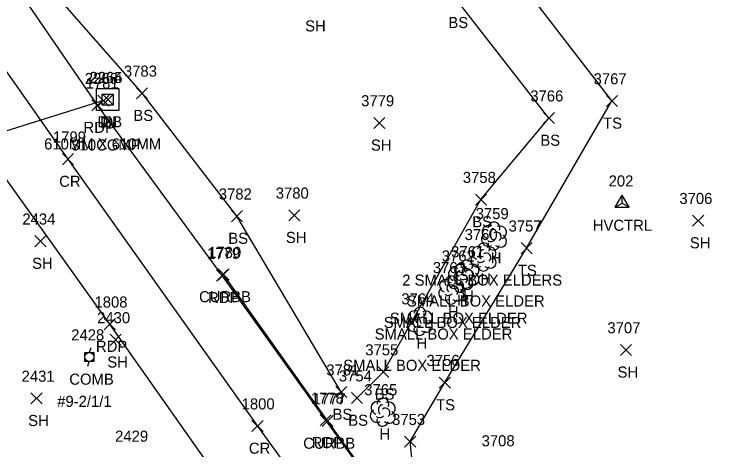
# Model space of a CAD drawing. Extents: x 1634209 to 1639641, y 608564 to 612258.
# Drawn here: x 1639024.2 to 1639153.3, y 611382 to 611460.6 of the extents above; entities that cross this region are included whole.
import ezdxf

# ---------------------------------------------------------------- set-up
doc = ezdxf.new("R2010")
doc.units = 0
for name, color, linetype in [('C_A', 7, 'Continuous'), ('C_I', 7, 'Continuous'), ('CPSM', 7, 'Continuous'), ('D_A', 7, 'Continuous'), ('D_C', 7, 'Continuous'), ('D_I', 7, 'Continuous'), ('D_TIC', 7, 'Continuous'), ('DCP', 7, 'Continuous'), ('DS', 7, 'Continuous'), ('L_A', 7, 'Continuous'), ('L_C', 7, 'Continuous'), ('L_I', 7, 'Continuous'), ('L_TIC', 7, 'Continuous'), ('LELB', 7, 'Continuous'), ('LTD', 7, 'Continuous'), ('P_A', 7, 'Continuous'), ('P_I', 7, 'Continuous'), ('P_TIC', 7, 'Continuous'), ('PET', 7, 'Continuous'), ('PRC', 7, 'Continuous'), ('R_A', 7, 'Continuous'), ('R_I', 7, 'Continuous'), ('R_TIC', 7, 'Continuous'), ('RC', 7, 'Continuous'), ('U_A', 7, 'Continuous'), ('U_C', 7, 'Continuous'), ('U_I', 7, 'Continuous'), ('UP', 7, 'Continuous')]:
    doc.layers.add(name, color=color, linetype=linetype)

msp = doc.modelspace()

# ---------------------------------------------------------------- linework, layer by layer
at = {"layer": 'CPSM'}
for p, q in [((1639132.51, 611425.81), (1639133.76, 611427.98)), ((1639135.01, 611425.81), (1639133.76, 611427.98)), ((1639133.76, 611426.54), (1639133.76, 611427.98)), ((1639132.51, 611425.81), (1639133.76, 611426.54)), ((1639132.51, 611425.81), (1639135.01, 611425.81)), ((1639133.76, 611426.54), (1639133.76, 611426.54)), ((1639133.76, 611426.54), (1639135.01, 611425.81))]:
    msp.add_line(p, q, dxfattribs=at)
at = {"layer": 'D_TIC'}
for points in [[(1639039.23, 611444.04), (1639041.23, 611446.04)], [(1639041.23, 611444.04), (1639039.23, 611446.04)], [(1639040.03, 611444.22), (1639042.03, 611446.22)], [(1639042.03, 611444.22), (1639040.03, 611446.22)]]:
    msp.add_lwpolyline(points, dxfattribs=at)
at = {"layer": 'DCP'}
msp.add_lwpolyline([(1639040.23, 611445.04), (1639009.01, 611435.28)], dxfattribs=at)
at = {"layer": 'DS'}
for p, q in [((1639038.98, 611447.23), (1639042.98, 611447.23)), ((1639038.98, 611443.23), (1639038.98, 611447.23)), ((1639039.98, 611444.23), (1639039.98, 611446.23)), ((1639039.98, 611446.23), (1639041.98, 611446.23)), ((1639041.98, 611446.23), (1639041.98, 611444.23)), ((1639042.98, 611447.23), (1639042.98, 611443.23)), ((1639040.98, 611445.23), (1639040.98, 611445.23)), ((1639040.98, 611445.23), (1639040.98, 611445.23)), ((1639041.98, 611444.23), (1639039.98, 611444.23)), ((1639042.98, 611443.23), (1639038.98, 611443.23))]:
    msp.add_line(p, q, dxfattribs=at)
at = {"layer": 'L_TIC'}
for points in [[(1639046.18, 611445.37), (1639048.18, 611447.37)], [(1639048.18, 611445.37), (1639046.18, 611447.37)], [(1639130.91, 611443.98), (1639132.91, 611445.98)], [(1639132.91, 611443.98), (1639130.91, 611445.98)], [(1639119.56, 611440.89), (1639121.56, 611442.89)], [(1639121.56, 611440.89), (1639119.56, 611442.89)], [(1639088.97, 611440.02), (1639090.97, 611442.02)], [(1639090.97, 611440.02), (1639088.97, 611442.02)], [(1639107.29, 611426.18), (1639109.29, 611428.18)], [(1639109.29, 611426.18), (1639107.29, 611428.18)], [(1639073.64, 611423.35), (1639075.64, 611425.35)], [(1639075.64, 611423.35), (1639073.64, 611425.35)], [(1639063.29, 611423.19), (1639065.29, 611425.19)], [(1639065.29, 611423.19), (1639063.29, 611425.19)], [(1639146.47, 611422.38), (1639148.47, 611424.38)], [(1639148.47, 611422.38), (1639146.47, 611424.38)], [(1639027.87, 611418.67), (1639029.87, 611420.67)], [(1639029.87, 611418.67), (1639027.87, 611420.67)], [(1639115.54, 611417.41), (1639117.54, 611419.41)], [(1639117.54, 611417.41), (1639115.54, 611419.41)], [(1639041.43, 611400.86), (1639043.43, 611402.86)], [(1639043.43, 611400.86), (1639041.43, 611402.86)], [(1639133.44, 611399.04), (1639135.44, 611401.04)], [(1639135.44, 611399.04), (1639133.44, 611401.04)], [(1639089.7, 611395.06), (1639091.7, 611397.06)], [(1639091.7, 611395.06), (1639089.7, 611397.06)], [(1639100.79, 611393.14), (1639102.79, 611395.14)], [(1639102.79, 611393.14), (1639100.79, 611395.14)], [(1639082.1, 611391.43), (1639084.1, 611393.43)], [(1639084.1, 611391.43), (1639082.1, 611393.43)], [(1639027.16, 611390.3), (1639029.16, 611392.3)], [(1639029.16, 611390.3), (1639027.16, 611392.3)], [(1639084.93, 611390.35), (1639086.93, 611392.35)], [(1639086.93, 611390.35), (1639084.93, 611392.35)], [(1639094.54, 611382.49), (1639096.54, 611384.49)], [(1639096.54, 611382.49), (1639094.54, 611384.49)]]:
    msp.add_lwpolyline(points, dxfattribs=at)
at = {"layer": 'LELB'}
for points in [[(1639184.5, 611390.62), (1639168.4, 611364.73), (1639149.1, 611336.39), (1639141.99, 611332.95), (1639134.34, 611331.83), (1639128.54, 611335.11), (1639121.61, 611339.72), (1639110.96, 611351.76), (1639096.78, 611371.21), (1639095.54, 611383.49), (1639101.79, 611394.14), (1639116.54, 611418.41), (1639131.91, 611444.98), (1639113.36, 611469.05), (1639093.12, 611490.67), (1639071.05, 611509.19), (1639055.5, 611526.42)], [(1639085.93, 611391.35), (1639090.7, 611396.06), (1639108.29, 611427.18), (1639120.56, 611441.89), (1639103.98, 611463.14), (1639086.83, 611480.83), (1639063.48, 611504.24), (1639051.54, 611519.63)], [(1639083.1, 611392.43), (1639064.29, 611424.19), (1639047.18, 611446.37), (1639027.15, 611469.33), (1639020.17, 611481.13), (1639024.02, 611486.6)]]:
    msp.add_lwpolyline(points, dxfattribs=at)
at = {"layer": 'LTD'}
for p, q in [((1639110.61, 611420.65), (1639110.61, 611420.65)), ((1639110.61, 611420.65), (1639110.61, 611420.65)), ((1639108.75, 611416.87), (1639108.75, 611416.87)), ((1639108.75, 611416.87), (1639108.75, 611416.87)), ((1639105.66, 611413.77), (1639105.66, 611413.77)), ((1639105.66, 611413.77), (1639105.66, 611413.77)), ((1639104.55, 611413), (1639104.55, 611413)), ((1639104.55, 611413), (1639104.55, 611413)), ((1639102.92, 611410.91), (1639102.92, 611410.91)), ((1639102.92, 611410.91), (1639102.92, 611410.91)), ((1639097.25, 611405.26), (1639097.25, 611405.26)), ((1639097.25, 611405.26), (1639097.25, 611405.26)), ((1639090.57, 611388.86), (1639090.57, 611388.86)), ((1639090.57, 611388.86), (1639090.57, 611388.86))]:
    msp.add_line(p, q, dxfattribs=at)
for centre in [(1639110.66, 611422.08), (1639108.8, 611418.3), (1639104.6, 611414.44), (1639105.71, 611415.2), (1639102.97, 611412.34), (1639097.3, 611406.69), (1639090.62, 611390.29)]:
    msp.add_arc(centre, 1.05, 335.5272, 180.9563, dxfattribs=at)
for centre, major_axis, ratio, start_param, end_param in [((1639109.82, 611421.31), (1.21, -0.51), 0.895232, 1.570796, 4.712389), ((1639110.41, 611421.1), (-0.208, -0.792), 0.645439, 3.141593, 6.283185), ((1639111.66, 611421.23), (-1.14, -0.48), 0.949671, 1.570796, 4.712389), ((1639109.53, 611419.94), (0.58, -1.04), 0.959034, 3.141593, 6.283185), ((1639111.11, 611420.48), (-0.5, 0.667), 0.989748, 3.141593, 6.283185), ((1639111.61, 611419.81), (-1.09, 0.79), 0.841452, 1.570796, 4.712389), ((1639107.96, 611417.53), (1.21, -0.51), 0.895232, 1.570796, 4.712389), ((1639110.61, 611419.15), (0.26, 1.06), 0.942809, 1.570796, 4.712389), ((1639110.16, 611419.9), (-0.625, -0.083), 0.423636, 0, 3.141593), ((1639108.54, 611417.32), (-0.208, -0.792), 0.645439, 3.141593, 6.283185), ((1639109.25, 611416.7), (-0.5, 0.667), 0.989748, 3.141593, 6.283185), ((1639109.79, 611417.45), (-1.14, -0.48), 0.949671, 1.570796, 4.712389), ((1639107.67, 611416.16), (0.58, -1.04), 0.959034, 3.141593, 6.283185), ((1639109.75, 611416.03), (-1.09, 0.79), 0.841452, 1.570796, 4.712389), ((1639103.76, 611413.67), (1.21, -0.51), 0.895232, 1.570796, 4.712389), ((1639104.87, 611414.43), (1.21, -0.51), 0.895232, 1.570796, 4.712389), ((1639105.45, 611414.22), (-0.208, -0.792), 0.645439, 3.141593, 6.283185), ((1639106.7, 611414.35), (-1.14, -0.48), 0.949671, 1.570796, 4.712389), ((1639108.75, 611415.37), (0.26, 1.06), 0.942809, 1.570796, 4.712389), ((1639108.29, 611416.12), (-0.625, -0.083), 0.423636, 0, 3.141593), ((1639104.58, 611413.06), (0.58, -1.04), 0.959034, 3.141593, 6.283185), ((1639104.34, 611413.46), (-0.208, -0.792), 0.645439, 3.141593, 6.283185), ((1639105.05, 611412.84), (-0.5, 0.667), 0.989748, 3.141593, 6.283185), ((1639105.59, 611413.59), (-1.14, -0.48), 0.949671, 1.570796, 4.712389), ((1639106.16, 611413.6), (-0.5, 0.667), 0.989748, 3.141593, 6.283185), ((1639106.66, 611412.93), (-1.09, 0.79), 0.841452, 1.570796, 4.712389), ((1639102.13, 611411.58), (1.21, -0.51), 0.895232, 1.570796, 4.712389), ((1639103.47, 611412.3), (0.58, -1.04), 0.959034, 3.141593, 6.283185), ((1639103.96, 611411.49), (-1.14, -0.48), 0.949671, 1.570796, 4.712389), ((1639105.66, 611412.27), (0.26, 1.06), 0.942809, 1.570796, 4.712389), ((1639105.2, 611413.02), (-0.625, -0.083), 0.423636, 0, 3.141593), ((1639105.55, 611412.17), (-1.09, 0.79), 0.841452, 1.570796, 4.712389), ((1639101.84, 611410.2), (0.58, -1.04), 0.959034, 3.141593, 6.283185), ((1639102.71, 611411.37), (-0.208, -0.792), 0.645439, 3.141593, 6.283185), ((1639103.42, 611410.74), (-0.5, 0.667), 0.989748, 3.141593, 6.283185), ((1639104.55, 611411.5), (0.26, 1.06), 0.942809, 1.570796, 4.712389), ((1639104.09, 611412.25), (-0.625, -0.083), 0.423636, 0, 3.141593), ((1639102.46, 611410.16), (-0.625, -0.083), 0.423636, 0, 3.141593), ((1639103.92, 611410.08), (-1.09, 0.79), 0.841452, 1.570796, 4.712389), ((1639102.92, 611409.41), (0.26, 1.06), 0.942809, 1.570796, 4.712389), ((1639096.46, 611405.92), (1.21, -0.51), 0.895232, 1.570796, 4.712389), ((1639097.04, 611405.72), (-0.208, -0.792), 0.645439, 3.141593, 6.283185), ((1639097.75, 611405.09), (-0.5, 0.667), 0.989748, 3.141593, 6.283185), ((1639098.29, 611405.84), (-1.14, -0.48), 0.949671, 1.570796, 4.712389), ((1639096.17, 611404.55), (0.58, -1.04), 0.959034, 3.141593, 6.283185), ((1639098.25, 611404.43), (-1.09, 0.79), 0.841452, 1.570796, 4.712389), ((1639097.25, 611403.76), (0.26, 1.06), 0.942809, 1.570796, 4.712389), ((1639096.79, 611404.51), (-0.625, -0.083), 0.423636, 0, 3.141593), ((1639089.78, 611389.53), (1.21, -0.51), 0.895232, 1.570796, 4.712389), ((1639091.61, 611389.44), (-1.14, -0.48), 0.949671, 1.570796, 4.712389), ((1639089.49, 611388.15), (0.58, -1.04), 0.959034, 3.141593, 6.283185), ((1639090.36, 611389.32), (-0.208, -0.792), 0.645439, 3.141593, 6.283185), ((1639091.07, 611388.69), (-0.5, 0.667), 0.989748, 3.141593, 6.283185), ((1639090.11, 611388.11), (-0.625, -0.083), 0.423636, 0, 3.141593), ((1639091.57, 611388.03), (-1.09, 0.79), 0.841452, 1.570796, 4.712389), ((1639090.57, 611387.36), (0.26, 1.06), 0.942809, 1.570796, 4.712389)]:
    msp.add_ellipse(centre, major_axis=major_axis, ratio=ratio, start_param=start_param, end_param=end_param, dxfattribs=at)
at = {"layer": 'P_TIC'}
for points in [[(1639038.15, 611443.21), (1639040.15, 611445.21)], [(1639040.15, 611443.21), (1639038.15, 611445.21)], [(1639032.82, 611433.48), (1639034.82, 611435.48)], [(1639034.82, 611433.48), (1639032.82, 611435.48)], [(1639060.61, 611412.48), (1639062.61, 611414.48)], [(1639062.61, 611412.48), (1639060.61, 611414.48)], [(1639040.38, 611403.69), (1639042.38, 611405.69)], [(1639042.38, 611403.69), (1639040.38, 611405.69)], [(1639079.31, 611386.33), (1639081.31, 611388.33)], [(1639081.31, 611386.33), (1639079.31, 611388.33)], [(1639067.01, 611385.3), (1639069.01, 611387.3)], [(1639069.01, 611385.3), (1639067.01, 611387.3)]]:
    msp.add_lwpolyline(points, dxfattribs=at)
at = {"layer": 'PET'}
for points in [[(1639148.64, 611331.08), (1639142.07, 611329.18), (1639135.69, 611328.74), (1639125.69, 611331.14), (1639119.17, 611334.87), (1639114.18, 611340.56), (1639098.76, 611361.78), (1639080.31, 611387.33), (1639061.61, 611413.48), (1639039.15, 611444.21), (1639014.33, 611480.36), (1638988.41, 611516.9), (1638963.39, 611551.84), (1638935.46, 611588.7), (1638918.51, 611609.36), (1638899.72, 611630.86), (1638874.4, 611653.86), (1638846.55, 611674.46), (1638833.14, 611682.53), (1638823.86, 611689.16)], [(1639117.36, 611283.37), (1639114.12, 611301.89), (1639095.51, 611328.5), (1639070.51, 611363.26), (1639041.38, 611404.69), (1639011.57, 611446.4), (1638984.33, 611485.14), (1638954.17, 611527.49), (1638934.32, 611554.77), (1638918.88, 611575.58), (1638893.27, 611605.66), (1638868.11, 611629.83), (1638836.66, 611652.85), (1638812.43, 611667.63)]]:
    msp.add_lwpolyline(points, dxfattribs=at)
at = {"layer": 'PRC'}
msp.add_lwpolyline([(1638818.79, 611678.83), (1638843.97, 611663.34), (1638876.43, 611637.38), (1638906.24, 611607.19), (1638934.14, 611573.69), (1638965.3, 611531.42), (1638998.82, 611484.34), (1639033.82, 611434.48), (1639068.01, 611386.3), (1639093.94, 611350.49), (1639111.89, 611325.37), (1639129.22, 611302.76)], dxfattribs=at)
at = {"layer": 'R_TIC'}
for points in [[(1639060.89, 611412.65), (1639062.89, 611414.65)], [(1639062.89, 611412.65), (1639060.89, 611414.65)], [(1639079.66, 611386.2), (1639081.66, 611388.2)], [(1639081.66, 611386.2), (1639079.66, 611388.2)]]:
    msp.add_lwpolyline(points, dxfattribs=at)
at = {"layer": 'RC'}
msp.add_lwpolyline([(1639125.9, 611331.25), (1639119.55, 611335.05), (1639114.37, 611340.71), (1639099.01, 611361.78), (1639080.66, 611387.2), (1639061.89, 611413.65)], dxfattribs=at)
at = {"layer": 'UP'}
for p, q in [((1639036.85, 611397.93), (1639036.85, 611399.6)), ((1639036.85, 611399.6), (1639038.52, 611399.6)), ((1639037.93, 611400.43), (1639037.68, 611399.6)), ((1639038.52, 611399.6), (1639038.52, 611397.93)), ((1639037.68, 611398.76), (1639037.68, 611398.76)), ((1639038.52, 611397.93), (1639036.85, 611397.93)), ((1639037.43, 611397.1), (1639037.68, 611397.93))]:
    msp.add_line(p, q, dxfattribs=at)
msp.add_circle((1639037.68, 611398.76), 0.833, dxfattribs=at)

# ---------------------------------------------------------------- texts
at = {"layer": 'C_A'}
msp.add_text('HVCTRL', height=2, dxfattribs=at).set_placement((1639128.46, 611421.54))
at = {"layer": 'C_I'}
msp.add_text('202', height=2, dxfattribs=at).set_placement((1639131.32, 611429.54))
at = {"layer": 'D_A'}
for s, p in [('DIB', (1639039.13, 611440.22)), ('DI', (1639040.04, 611440.23)), ('P', (1639039.61, 611440.04))]:
    msp.add_text(s, height=2, dxfattribs=at).set_placement(p)
at = {"layer": 'D_C'}
for s, p in [('610MM X 610MM', (1639029.53, 611436.23)), ('310CGMP', (1639034.44, 611436.04))]:
    msp.add_text(s, height=2, dxfattribs=at).set_placement(p)
at = {"layer": 'D_I'}
for s, p in [('2266', (1639036.87, 611448.04)), ('2264', (1639037.67, 611448.23)), ('2265', (1639037.72, 611448.22))]:
    msp.add_text(s, height=2, dxfattribs=at).set_placement(p)
at = {"layer": 'L_A'}
for s, p in [('SH', (1639076.59, 611457.53)), ('BS', (1639102.42, 611458.14)), ('BS', (1639045.62, 611441.37)), ('TS', (1639130.32, 611439.98)), ('BS', (1639119, 611436.89)), ('SH', (1639088.46, 611436.02)), ('BS', (1639106.73, 611422.18)), ('BS', (1639062.73, 611419.19)), ('SH', (1639073.13, 611419.35)), ('SH', (1639145.96, 611418.38)), ('H', (1639110.05, 611415.65)), ('SH', (1639027.36, 611414.67)), ('TS', (1639114.95, 611413.41)), ('H', (1639108.18, 611411.87)), ('H', (1639103.98, 611408)), ('H', (1639105.09, 611408.77)), ('H', (1639102.35, 611405.91)), ('H', (1639096.68, 611400.26)), ('SH', (1639040.92, 611396.86)), ('SH', (1639132.93, 611395.04)), ('BS', (1639089.14, 611391.06)), ('TS', (1639100.2, 611389.14)), ('BS', (1639081.54, 611387.43)), ('SH', (1639026.65, 611386.3)), ('BS', (1639084.37, 611386.35)), ('H', (1639090, 611383.86))]:
    msp.add_text(s, height=2, dxfattribs=at).set_placement(p)
at = {"layer": 'L_C'}
for s, p in [('2 SMALL BOX ELDERS', (1639094.1, 611411.65)), ('SMALL BOX ELDER', (1639094.96, 611407.87)), ('SMALL BOX ELDER', (1639090.76, 611404)), ('SMALL BOX ELDER', (1639091.87, 611404.77)), ('SMALL BOX ELDER', (1639089.13, 611401.91)), ('SMALL BOX ELDER', (1639083.46, 611396.26))]:
    msp.add_text(s, height=2, dxfattribs=at).set_placement(p)
at = {"layer": 'L_I'}
for s, p in [('3783', (1639043.92, 611449.37)), ('3767', (1639128.61, 611447.98)), ('3779', (1639086.7, 611444.02)), ('3766', (1639117.2, 611444.89)), ('3758', (1639105.03, 611430.18)), ('3782', (1639061.03, 611427.19)), ('3780', (1639071.3, 611427.35)), ('3706', (1639144.08, 611426.38)), ('3759', (1639107.35, 611423.65)), ('2434', (1639025.61, 611422.67)), ('3757', (1639113.28, 611421.41)), ('3760', (1639105.36, 611419.87)), ('3762', (1639101.24, 611416)), ('3761', (1639102.92, 611416.77)), ('3763', (1639099.61, 611413.91)), ('3764', (1639093.94, 611408.26)), ('2430', (1639039.09, 611404.86)), ('3707', (1639131.1, 611403.04)), ('3755', (1639087.44, 611399.06)), ('3756', (1639098.48, 611397.14)), ('3781', (1639080.41, 611395.43)), ('2431', (1639025.47, 611394.3)), ('3754', (1639082.67, 611394.35)), ('3765', (1639087.26, 611391.86)), ('3753', (1639092.28, 611386.49)), ('2429', (1639042.33, 611383.47)), ('3708', (1639108.42, 611382.64))]:
    msp.add_text(s, height=2, dxfattribs=at).set_placement(p)
at = {"layer": 'P_A'}
for s, p in [('RDP', (1639036.64, 611439.21)), ('CR', (1639032.25, 611429.48)), ('RDP', (1639059.1, 611408.48)), ('RDP', (1639038.87, 611399.69)), ('RDP', (1639077.8, 611382.33)), ('CR', (1639066.45, 611381.3))]:
    msp.add_text(s, height=2, dxfattribs=at).set_placement(p)
at = {"layer": 'P_I'}
for s, p in [('1781', (1639037.02, 611447.21)), ('1799', (1639031.12, 611437.48)), ('1779', (1639058.91, 611416.48)), ('1808', (1639038.61, 611407.69)), ('1778', (1639077.62, 611390.33)), ('1800', (1639065.15, 611389.3))]:
    msp.add_text(s, height=2, dxfattribs=at).set_placement(p)
at = {"layer": 'R_A'}
for p in [(1639057.47, 611408.65), (1639076.25, 611382.2)]:
    msp.add_text('CURBB', height=2, dxfattribs=at).set_placement(p)
at = {"layer": 'R_I'}
for s, p in [('1780', (1639059.11, 611416.65)), ('1777', (1639077.97, 611390.2))]:
    msp.add_text(s, height=2, dxfattribs=at).set_placement(p)
at = {"layer": 'U_A'}
msp.add_text('COMB', height=2, dxfattribs=at).set_placement((1639034.07, 611393.76))
at = {"layer": 'U_C'}
msp.add_text('#9-2/1/1', height=2, dxfattribs=at).set_placement((1639031.89, 611389.76))
at = {"layer": 'U_I'}
msp.add_text('2428', height=2, dxfattribs=at).set_placement((1639034.42, 611401.76))

doc.saveas('drawing.dxf')
